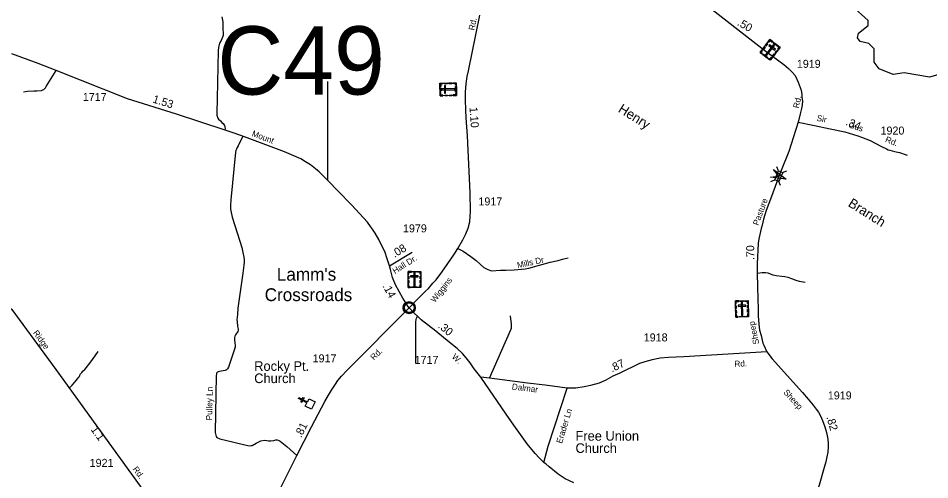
# Model space of a CAD drawing. Extents: x 2220236 to 2384410, y 720751 to 894131.
# Drawn here: x 2270312 to 2284543, y 784624 to 791836 of the extents above; entities that cross this region are included whole.
import ezdxf

# ---------------------------------------------------------------- set-up
doc = ezdxf.new("R2010")
doc.units = 0
doc.layers.add('Default', color=7, linetype='Continuous')

msp = doc.modelspace()

# ---------------------------------------------------------------- linework, layer by layer
at = {"layer": 'Default'}
for p, q in [((2275138, 790849), (2275139, 789309)), ((2282183, 789451), (2282156, 789514)), ((2282246, 789424), (2282310, 789450)), ((2282060, 789285), (2282124, 789311)), ((2282215, 789220), (2282189, 789284)), ((2276108, 787969), (2276460, 788182))]:
    msp.add_line(p, q, dxfattribs=at)
for points in [[(2280960, 792122), (2281969, 791330), (2282263, 791112), (2282337, 791052), (2282382, 791004), (2282443, 790939), (2282490, 790835), (2282533, 790710), (2282544, 790645), (2282548, 790602), (2282555, 790539), (2282551, 790485), (2282544, 790446), (2282522, 790340), (2282490, 790210)], [(2284669, 790949), (2284537, 790916), (2284144, 790980), (2283970, 790954), (2283752, 791044), (2283677, 791150), (2283674, 791357), (2283590, 791440), (2283457, 791473), (2283415, 791529), (2283431, 791604), (2283579, 791723), (2283579, 791798), (2283327, 792030)], [(2273490, 791860), (2273506, 791777), (2273506, 791662), (2273511, 791607), (2273513, 791582), (2273509, 791564), (2273502, 791538), (2273480, 791489), (2273453, 791444), (2273445, 791404), (2273437, 791380), (2273434, 791330), (2273419, 790582), (2273411, 790360), (2273414, 790319), (2273426, 790273), (2273440, 790257), (2273468, 790231), (2273488, 790209), (2273511, 790189), (2273531, 790158), (2273537, 790144), (2273541, 790102)], [(2276416, 787313), (2276544, 787447), (2276669, 787572), (2276718, 787613), (2276787, 787695), (2276837, 787746), (2276926, 787866), (2277111, 788139), (2277176, 788240), (2277254, 788374), (2277301, 788465), (2277335, 788556), (2277360, 788657), (2277366, 788742), (2277373, 788816), (2277368, 789107), (2277326, 789999), (2277306, 790279), (2277299, 790407), (2277295, 790559), (2277295, 790675), (2277299, 790756), (2277308, 790854), (2277319, 790926), (2277339, 791014), (2277520, 791885)], [(2276108, 787969), (2276068, 788091), (2276043, 788173), (2275943, 788379), (2275883, 788479), (2275843, 788539), (2275810, 788582), (2275764, 788648), (2275514, 788921), (2275299, 789140), (2275156, 789290), (2275139, 789308), (2275011, 789434), (2274951, 789484), (2274873, 789543), (2274795, 789593), (2274726, 789637), (2274651, 789671), (2274467, 789747), (2273844, 789981), (2273685, 790042), (2273529, 790092), (2272781, 790336), (2272018, 790577), (2270906, 791021), (2270623, 791128), (2270212, 791280)], [(2270396, 790688), (2270459, 790697), (2270555, 790702), (2270603, 790702), (2270675, 790709), (2270697, 790715), (2270711, 790721), (2270739, 790747), (2270749, 790767), (2270906, 791021)], [(2282490, 790210), (2282343, 789753), (2282223, 789459), (2282201, 789402)], [(2282490, 790210), (2282743, 790162), (2282987, 790109), (2283217, 790063), (2283418, 789999), (2283478, 789977), (2283612, 789923), (2283699, 789881), (2283789, 789832), (2283866, 789797), (2283896, 789781), (2283920, 789772), (2283994, 789756), (2284068, 789737), (2284188, 789694)], [(2273819, 789991), (2273746, 789842), (2273732, 789814), (2273718, 789790), (2273710, 789770), (2273705, 789742), (2273630, 788997), (2273625, 788913), (2273625, 788853), (2273629, 788827), (2273652, 788730), (2273737, 788468), (2273801, 788251), (2273822, 788151), (2273830, 788127), (2273838, 788071), (2273839, 788026), (2273835, 787978), (2273819, 787850), (2273742, 787305), (2273733, 787207), (2273727, 787125), (2273728, 787095), (2273736, 787021), (2273745, 786977), (2273745, 786963), (2273739, 786939), (2273702, 786891), (2273694, 786867), (2273688, 786845), (2273686, 786823), (2273695, 786753), (2273701, 786731), (2273701, 786713), (2273699, 786701), (2273690, 786663), (2273592, 786384), (2273577, 786360), (2273561, 786340), (2273543, 786332), (2273479, 786321), (2273453, 786315), (2273431, 786313), (2273421, 786306), (2273409, 786292), (2273408, 786276), (2273402, 786252), (2273386, 785363), (2273401, 785299), (2273415, 785283), (2273461, 785263), (2273918, 785156), (2273946, 785158), (2273966, 785162), (2274027, 785199), (2274099, 785231), (2274155, 785244), (2274195, 785240), (2274217, 785234), (2274253, 785233), (2274303, 785239), (2274331, 785246), (2274355, 785248), (2274381, 785238), (2274401, 785228), (2274504, 785145), (2274662, 785003)], [(2282201, 789402), (2282148, 789266), (2282071, 789051), (2281991, 788831), (2281946, 788697), (2281925, 788605), (2281910, 788548), (2281889, 788459), (2281877, 788390), (2281863, 788322), (2281851, 787998), (2281851, 787851), (2281854, 787640), (2281857, 787449), (2281863, 787294), (2281862, 787186), (2281873, 787057), (2281887, 786963), (2281909, 786880), (2281939, 786758), (2281953, 786726), (2281998, 786624)], [(2277176, 788240), (2277259, 788197), (2277377, 788115), (2277460, 788048), (2277527, 787987), (2277579, 787943), (2277643, 787911), (2277701, 787891), (2277842, 787901), (2277922, 787900), (2278052, 787903), (2278224, 787919), (2278284, 787929), (2278615, 788023), (2278740, 788052), (2278810, 788072), (2278896, 788091)], [(2276416, 787313), (2276394, 787335), (2276361, 787389), (2276316, 787461), (2276200, 787670), (2276155, 787786), (2276124, 787909), (2276108, 787969)], [(2281851, 787851), (2281927, 787864), (2281978, 787862), (2282017, 787856), (2282053, 787841), (2282091, 787829), (2282143, 787818), (2282235, 787807), (2282278, 787801), (2282328, 787789), (2282383, 787769), (2282451, 787744), (2282506, 787726), (2282596, 787712)], [(2269908, 787520), (2269978, 787491), (2270028, 787463), (2270058, 787438), (2270092, 787409), (2270108, 787390), (2270130, 787374), (2270214, 787286), (2270899, 786348), (2272213, 784526), (2272321, 784376), (2272374, 784306), (2272435, 784234), (2272446, 784223), (2272497, 784171), (2272567, 784124), (2272674, 784059), (2272743, 784037), (2272800, 784017), (2272899, 783995), (2273939, 783871)], [(2273939, 783871), (2274090, 784032), (2274175, 784134), (2274253, 784239), (2274304, 784311), (2274349, 784380), (2274662, 785003), (2274890, 785452), (2275100, 785845), (2275154, 785945), (2275203, 786026), (2275263, 786120), (2275303, 786176), (2275359, 786241), (2275446, 786338), (2276416, 787313)], [(2277534, 786226), (2277431, 786360), (2277366, 786454), (2277306, 786530), (2277250, 786597), (2277165, 786673), (2277042, 786776), (2276832, 786948), (2276600, 787125), (2276544, 787181), (2276495, 787230), (2276416, 787313)], [(2276517, 786452), (2276519, 787020), (2276520, 787097), (2276524, 787119), (2276524, 787131), (2276528, 787149), (2276544, 787181)], [(2277668, 786214), (2277999, 786959), (2278013, 786993), (2278014, 787011), (2278014, 787057), (2277997, 787187)], [(2271115, 786067), (2271155, 786105), (2271188, 786143), (2271215, 786178), (2271235, 786202), (2271249, 786216), (2271262, 786234), (2271265, 786239), (2271271, 786246), (2271275, 786258), (2271284, 786278), (2271303, 786303), (2271325, 786324), (2271349, 786346), (2271371, 786374), (2271428, 786445), (2271511, 786562), (2271559, 786631)], [(2281998, 786624), (2280701, 786547), (2280465, 786533), (2280334, 786527), (2280207, 786496), (2280096, 786468), (2280013, 786440), (2279702, 786290), (2279595, 786241), (2279484, 786182), (2279380, 786136), (2279248, 786099), (2279149, 786076), (2279015, 786055), (2278947, 786054), (2278883, 786058), (2278537, 786103), (2278265, 786136), (2277668, 786214), (2277534, 786226)], [(2281998, 786624), (2282084, 786514), (2282556, 785990), (2282645, 785883), (2282723, 785789), (2282768, 785730), (2282804, 785682), (2282838, 785624), (2282867, 785549), (2282907, 785452), (2282933, 785362), (2282951, 785259), (2282959, 785192), (2282957, 785136), (2282951, 785058), (2282935, 784982), (2282921, 784907), (2282897, 784817), (2282816, 784538), (2282669, 784131), (2282556, 783830), (2282403, 783455), (2282282, 783179), (2282112, 782802)], [(2278988, 784575), (2278850, 784639), (2278742, 784713), (2278600, 784827), (2278551, 784873), (2278523, 784891), (2278443, 784968), (2278382, 785035), (2278256, 785186), (2278051, 785480), (2277931, 785652), (2277534, 786226)], [(2278520, 784894), (2278587, 785149), (2278883, 786058)]]:
    msp.add_lwpolyline(points, dxfattribs=at)
for points in [[(2282048, 791501), (2282206, 791381), (2282052, 791178), (2281893, 791299)], [(2281977, 791408), (2282003, 791442), (2282012, 791435), (2281986, 791401)], [(2282117, 791412), (2282102, 791423), (2281979, 791262), (2281994, 791251)], [(2282022, 791467), (2282031, 791460), (2282050, 791486), (2282082, 791461), (2282089, 791470), (2282048, 791501)], [(2282039, 791422), (2282028, 791408), (2282121, 791336), (2282133, 791351)], [(2282107, 791456), (2282148, 791425), (2282141, 791416), (2282100, 791447)], [(2282180, 791346), (2282171, 791353), (2282190, 791379), (2282158, 791403), (2282165, 791412), (2282206, 791381)], [(2281920, 791279), (2281927, 791288), (2281909, 791301), (2281934, 791333), (2281925, 791340), (2281893, 791299)], [(2281936, 791354), (2281962, 791389), (2281971, 791382), (2281945, 791348)], [(2281946, 791273), (2282014, 791222), (2282007, 791213), (2281939, 791264)], [(2282087, 791243), (2282113, 791277), (2282122, 791270), (2282096, 791236)], [(2282127, 791295), (2282153, 791329), (2282162, 791323), (2282136, 791288)], [(2282026, 791198), (2282032, 791207), (2282050, 791194), (2282074, 791226), (2282083, 791219), (2282052, 791178)], [(2276898, 790624), (2276896, 790823), (2277151, 790825), (2277153, 790626)], [(2276940, 790823), (2276940, 790812), (2276908, 790811), (2276908, 790771), (2276897, 790771), (2276897, 790823)], [(2276898, 790698), (2276897, 790749), (2276909, 790750), (2276909, 790698)], [(2276927, 790733), (2276927, 790714), (2277130, 790716), (2277129, 790735)], [(2276966, 790665), (2276985, 790665), (2276984, 790783), (2276965, 790783)], [(2277013, 790812), (2276970, 790812), (2276970, 790823), (2277013, 790824)], [(2277079, 790813), (2277036, 790813), (2277036, 790824), (2277079, 790824)], [(2277151, 790792), (2277140, 790792), (2277140, 790814), (2277099, 790814), (2277099, 790825), (2277151, 790825)], [(2277141, 790683), (2277140, 790768), (2277152, 790768), (2277152, 790684)], [(2276942, 790624), (2276942, 790635), (2276909, 790635), (2276909, 790676), (2276898, 790675), (2276898, 790624)], [(2277016, 790625), (2276973, 790624), (2276973, 790636), (2277016, 790636)], [(2277083, 790625), (2277040, 790625), (2277040, 790636), (2277083, 790637)], [(2277153, 790659), (2277141, 790659), (2277141, 790637), (2277101, 790637), (2277101, 790626), (2277153, 790626)], [(2282106, 789470), (2282299, 789321), (2282057, 789353), (2282187, 789368)], [(2282124, 789311), (2282182, 789451), (2282247, 789423), (2282189, 789284)], [(2276398, 787881), (2276597, 787881), (2276597, 787626), (2276398, 787626)], [(2276398, 787837), (2276409, 787837), (2276409, 787870), (2276450, 787869), (2276450, 787881), (2276398, 787881)], [(2276472, 787881), (2276523, 787881), (2276523, 787869), (2276472, 787869)], [(2276597, 787837), (2276585, 787837), (2276585, 787869), (2276545, 787869), (2276545, 787881), (2276597, 787881)], [(2276398, 787763), (2276398, 787806), (2276409, 787806), (2276409, 787763)], [(2276398, 787696), (2276398, 787739), (2276409, 787739), (2276409, 787696)], [(2276438, 787813), (2276438, 787794), (2276556, 787794), (2276556, 787813)], [(2276507, 787851), (2276488, 787851), (2276488, 787649), (2276507, 787649)], [(2276585, 787764), (2276585, 787808), (2276597, 787808), (2276597, 787764)], [(2276585, 787698), (2276585, 787742), (2276597, 787742), (2276597, 787698)], [(2276431, 787626), (2276431, 787638), (2276409, 787638), (2276409, 787678), (2276398, 787678), (2276398, 787626)], [(2276455, 787637), (2276540, 787637), (2276540, 787626), (2276455, 787626)], [(2276564, 787626), (2276564, 787637), (2276586, 787637), (2276586, 787678), (2276597, 787678), (2276597, 787626)], [(2276339, 787325), (2276340, 787331), (2276342, 787338), (2276344, 787345), (2276347, 787351), (2276351, 787356), (2276354, 787361), (2276358, 787366), (2276363, 787370), (2276369, 787375), (2276374, 787379), (2276379, 787381), (2276384, 787384), (2276389, 787386), (2276395, 787388), (2276399, 787389), (2276404, 787390), (2276408, 787391), (2276415, 787391), (2276419, 787391), (2276425, 787391), (2276430, 787390), (2276435, 787389), (2276440, 787387), (2276445, 787385), (2276451, 787383), (2276458, 787379), (2276463, 787376), (2276468, 787371), (2276471, 787368), (2276475, 787364), (2276479, 787359), (2276482, 787355), (2276485, 787350), (2276488, 787345), (2276490, 787340), (2276491, 787335), (2276493, 787330), (2276494, 787324), (2276494, 787319), (2276495, 787313), (2276495, 787307), (2276494, 787302), (2276493, 787296), (2276491, 787290), (2276490, 787284), (2276487, 787279), (2276484, 787273), (2276481, 787268), (2276477, 787263), (2276473, 787258), (2276468, 787253), (2276463, 787249), (2276458, 787246), (2276453, 787243), (2276447, 787240), (2276439, 787237), (2276434, 787236), (2276427, 787235), (2276423, 787234), (2276418, 787234), (2276412, 787234), (2276408, 787234), (2276403, 787235), (2276397, 787236), (2276392, 787238), (2276387, 787240), (2276382, 787242), (2276378, 787244), (2276372, 787248), (2276366, 787252), (2276361, 787257), (2276357, 787261), (2276353, 787265), (2276350, 787270), (2276346, 787277), (2276345, 787280), (2276343, 787284), (2276340, 787292), (2276339, 787299), (2276338, 787305), (2276338, 787311), (2276338, 787316), (2276338, 787322)], [(2281508, 787418), (2281707, 787424), (2281714, 787169), (2281515, 787164)], [(2281509, 787375), (2281520, 787375), (2281520, 787408), (2281560, 787409), (2281560, 787420), (2281508, 787418)], [(2281511, 787301), (2281510, 787344), (2281521, 787344), (2281522, 787301)], [(2281550, 787351), (2281551, 787333), (2281669, 787336), (2281668, 787355)], [(2281582, 787420), (2281634, 787422), (2281634, 787410), (2281582, 787409)], [(2281618, 787392), (2281599, 787391), (2281604, 787189), (2281623, 787189)], [(2281708, 787380), (2281697, 787380), (2281696, 787412), (2281655, 787411), (2281655, 787422), (2281707, 787424)], [(2281699, 787307), (2281698, 787350), (2281709, 787351), (2281710, 787307)], [(2281513, 787234), (2281512, 787277), (2281523, 787277), (2281524, 787234)], [(2281548, 787165), (2281547, 787176), (2281525, 787176), (2281524, 787216), (2281513, 787216), (2281515, 787164)], [(2281572, 787177), (2281657, 787179), (2281657, 787168), (2281572, 787165)], [(2281681, 787168), (2281680, 787180), (2281702, 787180), (2281701, 787221), (2281712, 787221), (2281714, 787169)], [(2281700, 787241), (2281699, 787284), (2281711, 787285), (2281712, 787241)], [(2274794, 785775), (2274820, 785826), (2274752, 785861), (2274738, 785833), (2274723, 785840), (2274738, 785869), (2274685, 785896), (2274692, 785911), (2274746, 785883), (2274760, 785911), (2274775, 785904), (2274760, 785875), (2274827, 785840), (2274854, 785891), (2274948, 785842), (2274888, 785726)]]:
    msp.add_lwpolyline(points, close=True, dxfattribs=at)
for radius in [94.3, 76.7]:
    msp.add_circle((2276416, 787313), radius, dxfattribs=at)

# ---------------------------------------------------------------- texts
for s, height, p in [('C49', 1066.3, (2273420, 790643)), ('1919', 125, (2282468, 791061)), ('1717', 125, (2271320, 790543)), ('1920', 125, (2283775, 790018)), ('1917', 125, (2277497, 788911)), ('1979', 125, (2276319, 788490)), ("Lamm's", 200, (2274349, 787735)), ('Crossroads', 200, (2274159, 787416)), ('1918', 125, (2280078, 786786)), ('1917', 125, (2274908, 786459)), ('Rocky Pt.', 150, (2273996, 786326)), ('1717', 125, (2276501, 786435)), ('Church', 150, (2273996, 786135)), ('1919', 125, (2282952, 785880)), ('Free Union', 150, (2279012, 785235)), ('Church', 150, (2279012, 785044)), ('1921', 125, (2271427, 784826))]:
    msp.add_text(s, height=height, dxfattribs=at).set_placement(p)
for s, height, rotation, p in [('Rd.', 95, 78.5068, (2277434, 791639)), ('.50', 125, 329.9446, (2281527, 791733)), ('1.53', 125, 342.4779, (2272401, 790522)), ('Rd.', 95, 77.9969, (2282500, 790423)), ('1.10', 125, 274.0992, (2277357, 790445)), ('Henry', 150, 327.8694, (2279666, 790380)), ('Sir', 95, 347.6198, (2282771, 790235)), ('.34', 125, 337.5761, (2283221, 790172)), ('Gus', 95, 342.2789, (2283265, 790132)), ('Mount', 95, 339.3658, (2273951, 789997)), ('Rd.', 95, 337.999, (2283839, 789906)), ('Pasture', 95, 70.088, (2281867, 788590)), ('Branch', 150, 327.6874, (2283256, 788907)), ('.08', 125, 31.1421, (2276187, 788090)), ('.70', 125, 90.8991, (2281805, 788057)), ('Hall Dr.', 95, 32.4586, (2276193, 787836)), ('Mills Dr', 95, 12.3624, (2278112, 787929)), ('Wiggins', 95, 52.2076, (2276817, 787385)), ('.14', 125, 298.9574, (2275995, 787652)), ('.30', 125, 320.6596, (2276856, 787010)), ('Sheep', 95, 102.2505, (2281883, 786750)), ('Ridge', 95, 306.096, (2270536, 786919)), ('Rd.', 95, 44.6967, (2275865, 786485)), ('W.', 95, 316.4977, (2277073, 786535)), ('.87', 125, 25.9306, (2279582, 786301)), ('Rd.', 95, 2.9085, (2281496, 786387)), ('Pulley Ln', 95, 88.9864, (2273338, 785553)), ('Dalmar', 95, 353.0047, (2278014, 786036)), ('Sheep', 95, 312.1547, (2282252, 785984)), ('Erader Ln', 95, 73.3738, (2278801, 785184)), ('.82', 125, 286.1032, (2282928, 785603)), ('1.1', 125, 306.1818, (2271437, 785408)), ('.81', 125, 63.1086, (2274729, 785272)), ('Rd.', 95, 306.1818, (2272093, 784789))]:
    msp.add_text(s, height=height, rotation=rotation, dxfattribs=at).set_placement(p)

doc.saveas('drawing.dxf')
